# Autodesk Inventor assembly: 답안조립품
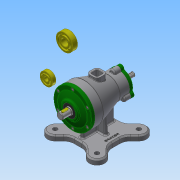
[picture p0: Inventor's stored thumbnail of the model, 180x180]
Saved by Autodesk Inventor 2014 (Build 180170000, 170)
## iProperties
Created: 2018-03
Part Number: 답안조립품
Document SubType Name: Assembly
Designer: 601-11
Author: 601-11
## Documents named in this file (13)
- C:\Users\601-11\Desktop\480308V1012\답안조립품.iam
- C:\Users\601-11\Desktop\480308V1012\본체.ipt
- C:\Users\601-11\Desktop\480308V1012\뒤커버.ipt
- C:\Users\601-11\Desktop\480308V1012\앞커버.ipt
- C:\Users\601-11\Desktop\480308V1012\베어링-6200.ipt
- C:\Users\601-11\Desktop\480308V1012\베어링-6203.ipt
- C:\Users\601-11\Desktop\480308V1012\축.ipt
- C:\Users\601-11\Desktop\480308V1012\키 5 x 5.ipt
- 키 5 x 5.ipt
- C:\Users\601-11\Desktop\480308V1012\볼트 M4 x 12.ipt
- 볼트 M4 x 12.ipt
- C:\Users\601-11\Desktop\480308V1012\오일 실 17 30 8.ipt
- C:\Users\601-11\Desktop\480308V1012\오일 실 10 20 7.ipt
